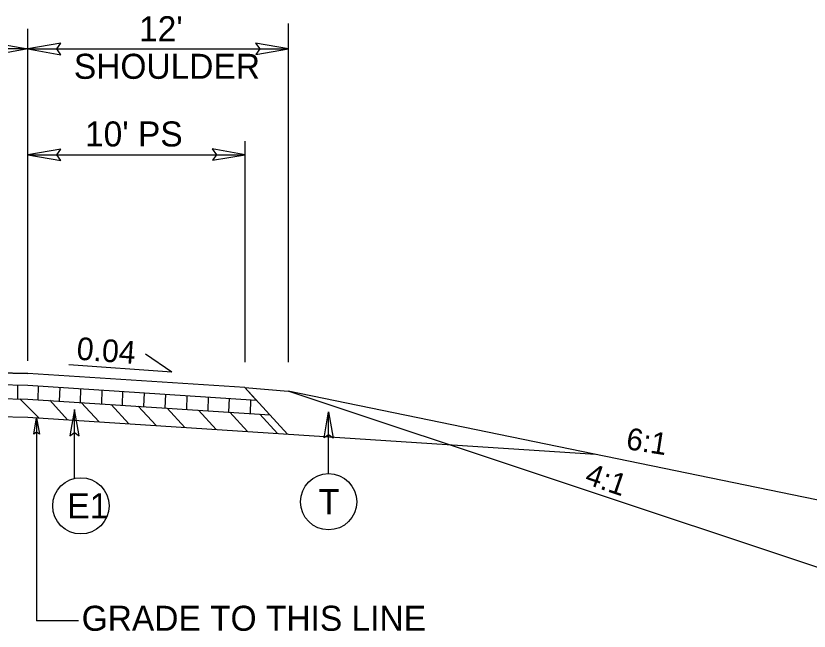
# Model space of a CAD drawing. Extents: x 2176024 to 2177225, y 75947 to 76635.
# Drawn here: x 2176341.28 to 2176377.8, y 76555.13 to 76583.47 of the extents above; entities that cross this region are included whole.
import ezdxf

# ---------------------------------------------------------------- set-up
doc = ezdxf.new("R2010")
doc.units = 0
for name, color, linetype in [('Old_Level_1', 7, 'Continuous'), ('Old_Level_11', 7, 'Continuous'), ('Prop Dimension', 7, 'Continuous'), ('Typical Pavement Slope CELL', 7, 'Continuous'), ('Typical Pavement Slope Information CELL', 7, 'Continuous'), ('Typical Shoulder Slope CELL', 7, 'Continuous'), ('Typical Slope Point Local CELL', 7, 'Continuous'), ('Typical Terminator CELL', 7, 'Continuous'), ('Typical Text General CELL', 7, 'Continuous')]:
    doc.layers.add(name, color=color, linetype=linetype)

msp = doc.modelspace()

# ---------------------------------------------------------------- linework, layer by layer
at = {"layer": 'Old_Level_1'}
for p, q in [((2176341.375, 76565.826), (2176341.37, 76566.466)), ((2176342.311, 76565.787), (2176342.334, 76566.43)), ((2176343.298, 76565.719), (2176343.321, 76566.365)), ((2176344.253, 76565.662), (2176344.276, 76566.302)), ((2176345.24, 76565.59), (2176345.264, 76566.237)), ((2176346.19, 76565.529), (2176346.213, 76566.175)), ((2176347.177, 76565.472), (2176347.2, 76566.11)), ((2176348.163, 76565.399), (2176348.186, 76566.046)), ((2176349.15, 76565.338), (2176349.173, 76565.981)), ((2176350.137, 76565.27), (2176350.16, 76565.916)), ((2176342.342, 76564.953), (2176341.467, 76565.827)), ((2176343.667, 76564.863), (2176342.848, 76565.759)), ((2176345.112, 76564.765), (2176344.294, 76565.659)), ((2176346.486, 76564.68), (2176345.678, 76565.563)), ((2176351.092, 76565.213), (2176351.116, 76565.853)), ((2176352.079, 76565.141), (2176352.103, 76565.789)), ((2176347.742, 76564.592), (2176346.915, 76565.482)), ((2176349.064, 76564.511), (2176348.255, 76565.396)), ((2176350.507, 76564.414), (2176349.688, 76565.31)), ((2176351.951, 76564.316), (2176351.133, 76565.21)), ((2176353.325, 76564.231), (2176352.518, 76565.114))]:
    msp.add_line(p, q, dxfattribs=at)
at = {"layer": 'Old_Level_11'}
for p, q in [((2176343.987, 76562.196), (2176343.987, 76565.329)), ((2176355.683, 76562.383), (2176355.683, 76565.225))]:
    msp.add_line(p, q, dxfattribs=at)
for points in [[(2176344.194, 76564.129), (2176343.987, 76565.329), (2176343.774, 76564.122), (2176343.987, 76564.275)], [(2176355.477, 76564.025), (2176355.683, 76565.225), (2176355.897, 76564.018), (2176355.683, 76564.172)]]:
    msp.add_lwpolyline(points, close=True, dxfattribs=at)
for centre in [(2176355.683, 76561.087), (2176344.278, 76560.9)]:
    msp.add_circle(centre, 1.296, dxfattribs=at)
at = {"layer": 'Prop Dimension'}
for p, q in [((2176353.841, 76567.523), (2176353.841, 76583.109)), ((2176341.841, 76567.585), (2176341.841, 76582.873)), ((2176341.841, 76581.946), (2176329.841, 76581.946)), ((2176341.841, 76581.946), (2176353.841, 76581.946)), ((2176351.841, 76567.523), (2176351.841, 76577.691)), ((2176341.841, 76577.073), (2176351.841, 76577.073)), ((2176342.24, 76564.959), (2176342.24, 76555.604)), ((2176344.174, 76555.604), (2176342.24, 76555.604))]:
    msp.add_line(p, q, dxfattribs=at)
at = {"layer": 'Typical Pavement Slope CELL'}
for p, q in [((2176351.822, 76566.345), (2176341.841, 76567)), ((2176329.841, 76566.712), (2176341.841, 76566.462)), ((2176341.841, 76566.462), (2176352.348, 76565.772)), ((2176351.822, 76566.345), (2176353.793, 76564.201)), ((2176329.841, 76566.068), (2176341.841, 76565.818)), ((2176380.829, 76560.623), (2176353.822, 76566.185)), ((2176341.841, 76565.818), (2176352.978, 76565.087)), ((2176341.841, 76564.986), (2176367.973, 76563.271))]:
    msp.add_line(p, q, dxfattribs=at)
at = {"layer": 'Typical Pavement Slope Information CELL'}
for q in [(2176347.246, 76567.882), (2176343.723, 76567.386)]:
    msp.add_line((2176348.468, 76567.06), q, dxfattribs=at)
at = {"layer": 'Typical Shoulder Slope CELL'}
for p, q in [((2176351.822, 76566.345), (2176353.822, 76566.185)), ((2176380.829, 76557.183), (2176353.822, 76566.185)), ((2176329.841, 76565.236), (2176341.841, 76564.986))]:
    msp.add_line(p, q, dxfattribs=at)
at = {"layer": 'Typical Slope Point Local CELL'}
for p, q in [((2176329.841, 76567.25), (2176341.841, 76567)), ((2176341.841, 76567), (2176329.841, 76567.25)), ((2176351.822, 76566.345), (2176341.841, 76567)), ((2176329.841, 76566.712), (2176341.841, 76566.462)), ((2176341.841, 76566.462), (2176352.348, 76565.772)), ((2176352.348, 76565.772), (2176351.822, 76566.345))]:
    msp.add_line(p, q, dxfattribs=at)
at = {"layer": 'Typical Terminator CELL'}
for points in [[(2176340.331, 76582.206), (2176341.841, 76581.946), (2176340.323, 76581.677), (2176340.516, 76581.946)], [(2176343.35, 76582.206), (2176341.841, 76581.946), (2176343.359, 76581.677), (2176343.166, 76581.946)], [(2176352.331, 76581.686), (2176353.841, 76581.946), (2176352.323, 76582.214), (2176352.516, 76581.946)], [(2176343.35, 76577.333), (2176341.841, 76577.073), (2176343.359, 76576.805), (2176343.166, 76577.073)], [(2176350.331, 76576.814), (2176351.841, 76577.073), (2176350.323, 76577.342), (2176350.516, 76577.073)], [(2176342.11, 76564.205), (2176342.24, 76564.959), (2176342.374, 76564.2), (2176342.24, 76564.297)]]:
    msp.add_lwpolyline(points, close=True, dxfattribs=at)

# ---------------------------------------------------------------- texts
at = {"layer": 'Old_Level_11'}
for s, rotation, p in [('T', 359.9997, (2176355.226, 76560.507)), ('E1', 0.0003, (2176343.649, 76560.32))]:
    msp.add_text(s, height=1.16, rotation=rotation, dxfattribs=at).set_placement(p)
at = {"layer": 'Typical Pavement Slope Information CELL'}
msp.add_text('0.04', height=1.0429, rotation=355.7342, dxfattribs=at).set_placement((2176344.056, 76567.635))
at = {"layer": 'Typical Slope Point Local CELL'}
for s, rotation, p in [('6:1', 351.0418, (2176369.335, 76563.519)), ('4:1', 341.041, (2176367.419, 76561.938))]:
    msp.add_text(s, height=1.0064, rotation=rotation, dxfattribs=at).set_placement(p)
at = {"layer": 'Typical Text General CELL'}
for s, height, p in [("12' ", 1.1533, (2176346.956, 76582.296)), ('SHOULDER', 1.1533, (2176343.954, 76580.566)), ("10' PS", 1.1533, (2176344.468, 76577.45)), ('GRADE TO THIS LINE', 1.15334, (2176344.313, 76555.144))]:
    msp.add_text(s, height=height, dxfattribs=at).set_placement(p)

doc.saveas('drawing.dxf')
